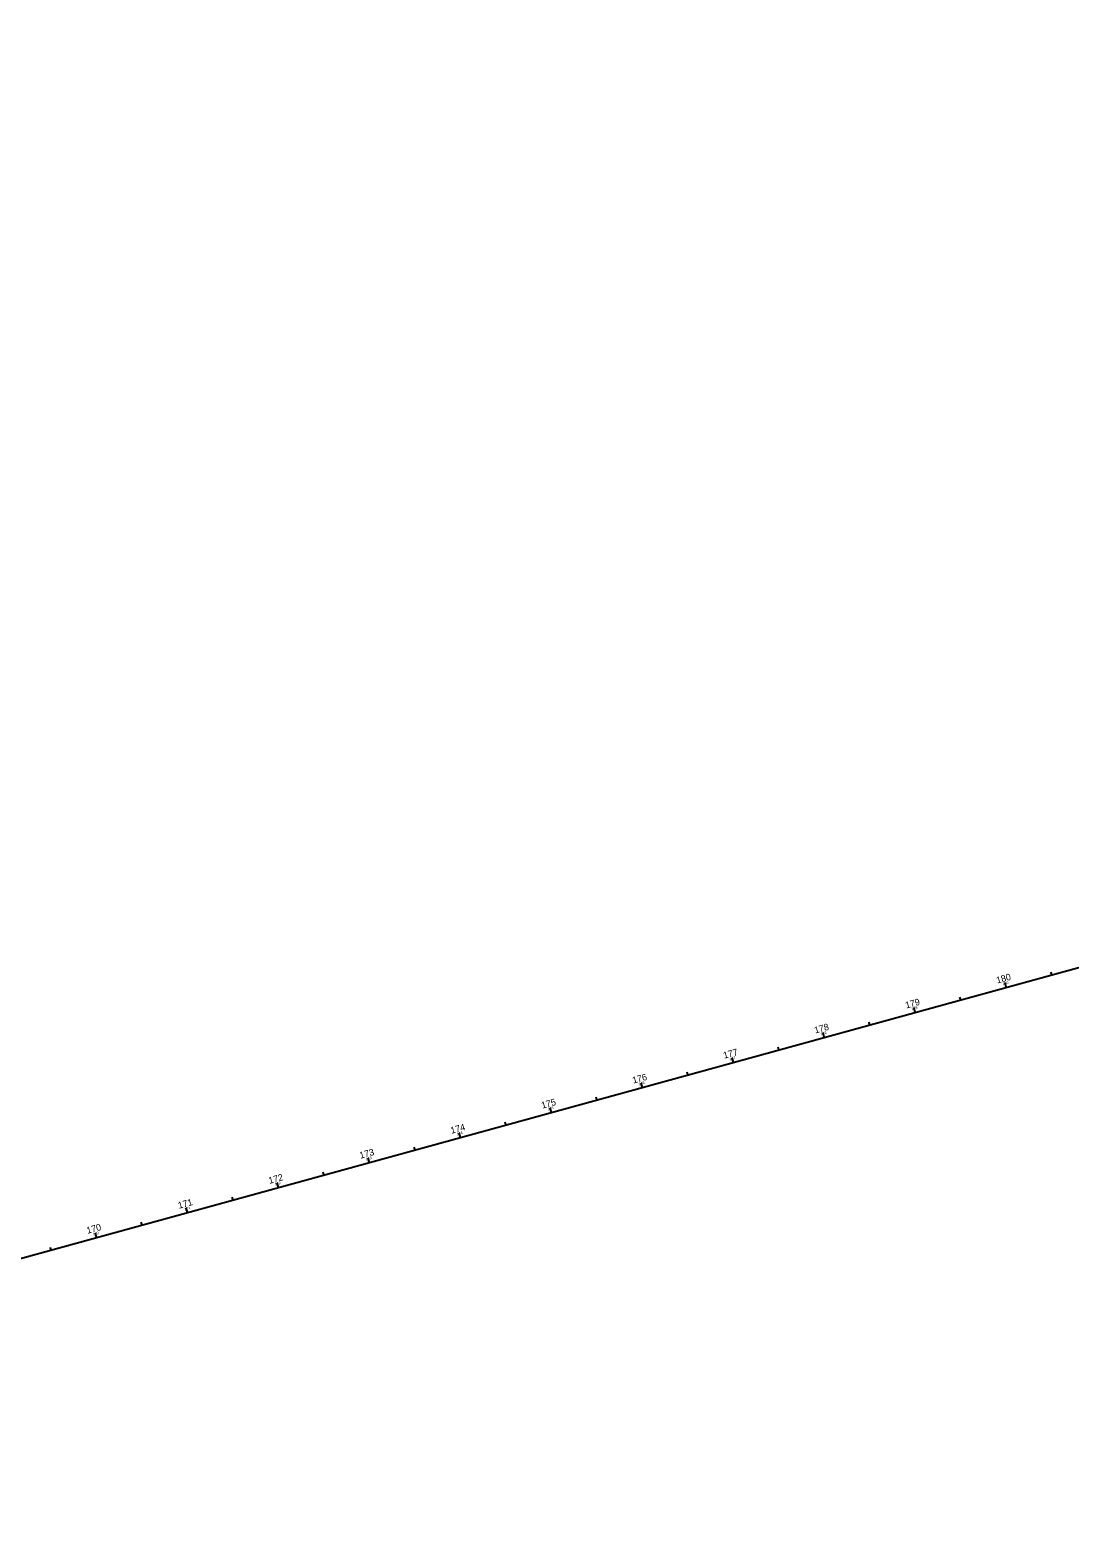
# Model space of a CAD drawing. Extents: x 2129507 to 2138391, y 657622 to 659877.
# Drawn here: x 2130623 to 2131725, y 657717 to 659316 of the extents above; entities that cross this region are included whole.
import ezdxf

# ---------------------------------------------------------------- set-up
doc = ezdxf.new("R2010")
doc.units = 0
for name, color, linetype in [('Default', 7, 'Continuous'), ('GE_X_Alignment_1000_Stations', 7, 'Continuous'), ('GE_X_Alignment_100_Stations', 7, 'Continuous'), ('GE_X_Alignment_500_Stations', 7, 'Continuous'), ('GE_X_CL_20', 7, 'Continuous'), ('MT_P_CL_20', 7, 'Continuous')]:
    doc.layers.add(name, color=color, linetype=linetype)

msp = doc.modelspace()

# ---------------------------------------------------------------- linework, layer by layer
at = {"layer": 'Default'}
for centre in [(2131657.7, 658301), (2131657.7, 658301), (2131657.7, 658301), (2131561.3, 658274.4), (2131464.9, 658247.9), (2131368.5, 658221.4), (2131272.1, 658194.8), (2131175.7, 658168.3), (2131175.7, 658168.3), (2131079.3, 658141.8), (2130982.8, 658115.2), (2130886.4, 658088.7), (2130790, 658062.1), (2130693.6, 658035.6), (2130693.6, 658035.6), (2130693.6, 658035.6)]:
    msp.add_circle(centre, 0.0000833, dxfattribs=at)
at = {"layer": 'GE_X_Alignment_1000_Stations'}
for p, q in [((2131657.7, 658301), (2131656.4, 658305.8)), ((2131175.7, 658168.3), (2131174.9, 658171.2)), ((2130693.6, 658035.6), (2130692.3, 658040.4))]:
    msp.add_line(p, q, dxfattribs=at)
at = {"layer": 'GE_X_Alignment_100_Stations'}
for p, q in [((2131657.7, 658301), (2131656.4, 658305.8)), ((2131706, 658314.2), (2131705.2, 658317.1)), ((2131609.5, 658287.7), (2131608.7, 658290.6)), ((2131561.3, 658274.4), (2131560, 658279.3)), ((2131513.1, 658261.2), (2131512.3, 658264.1)), ((2131464.9, 658247.9), (2131463.6, 658252.7)), ((2131368.5, 658221.4), (2131367.2, 658226.2)), ((2131416.7, 658234.6), (2131415.9, 658237.5)), ((2131320.3, 658208.1), (2131319.5, 658211)), ((2131272.1, 658194.8), (2131270.8, 658199.6)), ((2131223.9, 658181.6), (2131223.1, 658184.5)), ((2131175.7, 658168.3), (2131174.3, 658173.1)), ((2131079.3, 658141.8), (2131077.9, 658146.6)), ((2131127.5, 658155), (2131126.7, 658157.9)), ((2131031.1, 658128.5), (2131030.3, 658131.4)), ((2130982.8, 658115.2), (2130981.5, 658120)), ((2130934.6, 658102), (2130933.8, 658104.8)), ((2130886.4, 658088.7), (2130885.1, 658093.5)), ((2130790, 658062.1), (2130788.7, 658067)), ((2130838.2, 658075.4), (2130837.4, 658078.3)), ((2130741.8, 658048.9), (2130741, 658051.8)), ((2130693.6, 658035.6), (2130692.3, 658040.4)), ((2130645.4, 658022.3), (2130644.6, 658025.2))]:
    msp.add_line(p, q, dxfattribs=at)
at = {"layer": 'GE_X_Alignment_500_Stations'}
for p, q in [((2131657.7, 658301), (2131656.4, 658305.8)), ((2131561.3, 658274.4), (2131560.5, 658277.3)), ((2131464.9, 658247.9), (2131464.1, 658250.8)), ((2131368.5, 658221.4), (2131367.7, 658224.3)), ((2131272.1, 658194.8), (2131271.3, 658197.7)), ((2131175.7, 658168.3), (2131174.3, 658173.1)), ((2131079.3, 658141.8), (2131078.5, 658144.6)), ((2130982.8, 658115.2), (2130982, 658118.1)), ((2130886.4, 658088.7), (2130885.6, 658091.6)), ((2130790, 658062.1), (2130789.2, 658065)), ((2130693.6, 658035.6), (2130692.3, 658040.4))]:
    msp.add_line(p, q, dxfattribs=at)
at = {"layer": 'GE_X_CL_20'}
for p, q in [((2129536.9, 657717.3), (2135344.6, 659315.7)), ((2131706, 658314.2), (2131705.4, 658316.2)), ((2131609.5, 658287.7), (2131609, 658289.6)), ((2131657.7, 658301), (2131657.2, 658302.9)), ((2131561.3, 658274.4), (2131560.8, 658276.4)), ((2131513.1, 658261.2), (2131512.6, 658263.1)), ((2131464.9, 658247.9), (2131464.4, 658249.8)), ((2131416.7, 658234.6), (2131416.2, 658236.6)), ((2131320.3, 658208.1), (2131319.8, 658210)), ((2131368.5, 658221.4), (2131368, 658223.3)), ((2131272.1, 658194.8), (2131271.6, 658196.8)), ((2131223.9, 658181.6), (2131223.3, 658183.5)), ((2131175.7, 658168.3), (2131175.1, 658170.2)), ((2131127.5, 658155), (2131126.9, 658157)), ((2131031.1, 658128.5), (2131030.5, 658130.4)), ((2131079.3, 658141.8), (2131078.7, 658143.7)), ((2130982.8, 658115.2), (2130982.3, 658117.1)), ((2130934.6, 658102), (2130934.1, 658103.9)), ((2130886.4, 658088.7), (2130885.9, 658090.6)), ((2130838.2, 658075.4), (2130837.7, 658077.3)), ((2130741.8, 658048.9), (2130741.3, 658050.8)), ((2130790, 658062.1), (2130789.5, 658064.1)), ((2130693.6, 658035.6), (2130693.1, 658037.5)), ((2130645.4, 658022.3), (2130644.9, 658024.3))]:
    msp.add_line(p, q, dxfattribs=at)
at = {"layer": 'MT_P_CL_20'}
msp.add_line((2129536.9, 657717.3), (2135344.6, 659315.7), dxfattribs=at)

# ---------------------------------------------------------------- texts
at = {"layer": 'GE_X_Alignment_1000_Stations'}
for s, p in [('180', (2131648.2, 658304.9)), ('170', (2130684, 658039.6))]:
    msp.add_text(s, height=7, rotation=15.3886, dxfattribs=at).set_placement(p)
at = {"layer": 'GE_X_Alignment_100_Stations'}
for s, p in [('180', (2131648.2, 658304.9)), ('179', (2131551.8, 658278.4)), ('178', (2131455.3, 658251.9)), ('177', (2131358.8, 658225.2)), ('176', (2131262.5, 658198.8)), ('175', (2131166, 658172.2)), ('174', (2131069.8, 658145.6)), ('173', (2130973.3, 658119.2)), ('172', (2130876.9, 658092.5)), ('171', (2130780.9, 658066.1)), ('170', (2130684, 658039.6))]:
    msp.add_text(s, height=7, rotation=15.3886, dxfattribs=at).set_placement(p)
at = {"layer": 'GE_X_Alignment_500_Stations'}
for s, p in [('180', (2131648.2, 658304.9)), ('175', (2131166, 658172.2)), ('170', (2130684, 658039.6))]:
    msp.add_text(s, height=7, rotation=15.3886, dxfattribs=at).set_placement(p)
at = {"layer": 'GE_X_CL_20'}
for s, p in [('180', (2131654.1, 658303.1)), ('179', (2131557.7, 658276.6)), ('178', (2131461.4, 658250)), ('177', (2131364.8, 658223.5)), ('176', (2131268.5, 658196.9)), ('175', (2131172.1, 658170.4)), ('174', (2131075.7, 658143.9)), ('173', (2130979.2, 658117.3)), ('172', (2130882.8, 658090.8)), ('171', (2130786.9, 658064.4)), ('170', (2130689.9, 658037.7))]:
    msp.add_text(s, height=2.8, rotation=15.3886, dxfattribs=at).set_placement(p)

doc.saveas('drawing.dxf')
